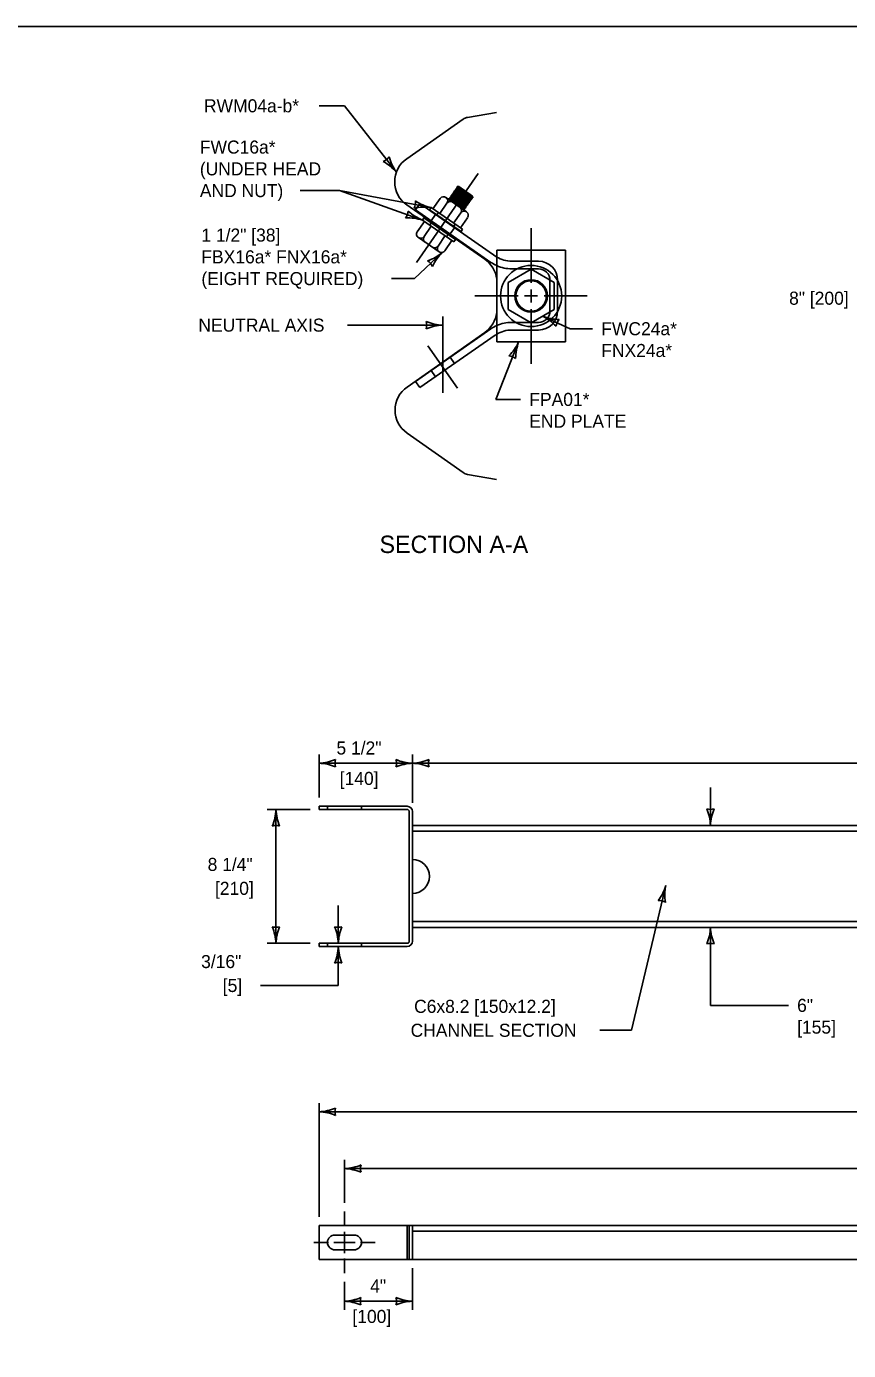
# Model space of a CAD drawing. Extents: x 49991.4 to 50021, y 49987.6 to 50011.4.
# Drawn here: x 50007.52 to 50011.29, y 49992.92 to 49999 of the extents above; entities that cross this region are included whole.
import ezdxf

# ---------------------------------------------------------------- set-up
doc = ezdxf.new("R2010")
doc.units = 0
for name, color, linetype in [('Level 1', 7, 'Continuous'), ('Level 2', 7, 'Continuous'), ('Level 3', 7, 'Continuous'), ('Level 4', 7, 'Continuous'), ('Level 5', 7, 'Continuous')]:
    doc.layers.add(name, color=color, linetype=linetype)

msp = doc.modelspace()

# ---------------------------------------------------------------- linework, layer by layer
at = {"layer": 'Level 1'}
for p, q in [((50009.5226, 49998.573), (50009.2635, 49998.3913)), ((50009.6759, 49998.6042), (50009.5436, 49998.5817)), ((50009.3838, 49998.1614), (50009.4176, 49998.2094)), ((50009.5389, 49998.1471), (50009.4441, 49998.2139)), ((50009.463, 49998.2071), (50009.4563, 49998.2067)), ((50009.4563, 49998.2067), (50009.4667, 49998.198)), ((50009.4684, 49998.2143), (50009.4612, 49998.2134)), ((50009.463, 49998.2071), (50009.4612, 49998.2134)), ((50009.4612, 49998.2134), (50009.526, 49998.163)), ((50009.463, 49998.2071), (50009.5278, 49998.1563)), ((50009.4729, 49998.2215), (50009.4657, 49998.2211)), ((50009.4684, 49998.2143), (50009.4657, 49998.2211)), ((50009.4657, 49998.2211), (50009.531, 49998.1698)), ((50009.4684, 49998.2143), (50009.5332, 49998.163)), ((50009.4779, 49998.2283), (50009.4711, 49998.2278)), ((50009.4729, 49998.2215), (50009.4711, 49998.2278)), ((50009.4711, 49998.2278), (50009.5359, 49998.177)), ((50009.4729, 49998.2215), (50009.5382, 49998.1702)), ((50009.4833, 49998.2355), (50009.4761, 49998.235)), ((50009.4779, 49998.2283), (50009.4761, 49998.235)), ((50009.4761, 49998.235), (50009.5409, 49998.1837)), ((50009.4779, 49998.2283), (50009.5431, 49998.1774)), ((50009.4882, 49998.2427), (50009.4806, 49998.2418)), ((50009.4833, 49998.2355), (50009.4806, 49998.2418)), ((50009.4806, 49998.2418), (50009.5458, 49998.1909)), ((50009.4833, 49998.2355), (50009.5481, 49998.1842)), ((50009.4927, 49998.2494), (50009.486, 49998.249)), ((50009.4882, 49998.2427), (50009.486, 49998.249)), ((50009.486, 49998.249), (50009.5508, 49998.1977)), ((50009.4882, 49998.2427), (50009.553, 49998.1914)), ((50009.4977, 49998.2562), (50009.4909, 49998.2566)), ((50009.4927, 49998.2494), (50009.4909, 49998.2566)), ((50009.4909, 49998.2566), (50009.5562, 49998.2053)), ((50009.4927, 49998.2494), (50009.5575, 49998.1986)), ((50009.4959, 49998.2634), (50009.5611, 49998.2121)), ((50009.5031, 49998.2634), (50009.4959, 49998.2634)), ((50009.4977, 49998.2562), (50009.4959, 49998.2634)), ((50009.4977, 49998.2562), (50009.5629, 49998.2058)), ((50009.5031, 49998.2634), (50009.5679, 49998.2125)), ((50009.5656, 49998.2193), (50009.5031, 49998.2634)), ((50009.5629, 49998.2058), (50009.5562, 49998.2053)), ((50009.5575, 49998.1986), (50009.5562, 49998.2053)), ((50009.5679, 49998.2125), (50009.5611, 49998.2121)), ((50009.5629, 49998.2058), (50009.5611, 49998.2121)), ((50009.5679, 49998.2125), (50009.5656, 49998.2193)), ((50009.2637, 49998.1795), (50009.622, 49997.9301)), ((50009.3237, 49998.1852), (50009.3034, 49998.1564)), ((50009.6509, 49997.9154), (50009.3034, 49998.1564)), ((50009.6774, 49997.9399), (50009.3237, 49998.1852)), ((50009.3685, 49998.1568), (50009.3753, 49998.1672)), ((50009.3685, 49998.1568), (50009.5134, 49998.0574)), ((50009.3753, 49998.1672), (50009.5202, 49998.0677)), ((50009.4157, 49998.1395), (50009.4486, 49998.1873)), ((50009.5278, 49998.1563), (50009.526, 49998.163)), ((50009.5332, 49998.163), (50009.526, 49998.163)), ((50009.5382, 49998.1702), (50009.531, 49998.1698)), ((50009.5332, 49998.163), (50009.531, 49998.1698)), ((50009.5431, 49998.1774), (50009.5359, 49998.177)), ((50009.5382, 49998.1702), (50009.5359, 49998.177)), ((50009.5481, 49998.1842), (50009.5409, 49998.1837)), ((50009.5431, 49998.1774), (50009.5409, 49998.1837)), ((50009.553, 49998.1914), (50009.5458, 49998.1909)), ((50009.5481, 49998.1842), (50009.5458, 49998.1909)), ((50009.5575, 49998.1986), (50009.5508, 49998.1977)), ((50009.553, 49998.1914), (50009.5508, 49998.1977)), ((50009.3449, 49998.1033), (50009.312, 49998.0556)), ((50009.3358, 49998.1096), (50009.3426, 49998.12)), ((50009.3358, 49998.1096), (50009.4807, 49998.0102)), ((50009.3426, 49998.12), (50009.4875, 49998.0205)), ((50009.3697, 49998.0863), (50009.3767, 49998.0966)), ((50009.3758, 49998.1062), (50009.3957, 49998.1352)), ((50009.4024, 49998.1335), (50009.4093, 49998.1438)), ((50009.4791, 49998.0959), (50009.5116, 49998.1423)), ((50009.4792, 49998.0808), (50009.4865, 49998.0908)), ((50009.5107, 49998.0742), (50009.5434, 49998.1207)), ((50009.4126, 49997.9637), (50009.317, 49998.0291)), ((50009.3764, 49998.0817), (50009.3435, 49998.034)), ((50009.4399, 49998.0382), (50009.4074, 49997.9904)), ((50009.4466, 49998.0336), (50009.4538, 49998.0436)), ((50009.4626, 49998.046), (50009.4832, 49998.0746)), ((50009.5134, 49998.0574), (50009.5202, 49998.0677)), ((50009.4717, 49998.0164), (50009.4389, 49997.9688)), ((50009.4807, 49998.0102), (50009.4875, 49998.0205)), ((50009.6774, 49997.9719), (50009.9933, 49997.9719)), ((50009.6774, 49997.5497), (50009.6774, 49997.9719)), ((50009.9933, 49997.9719), (50009.9933, 49997.5497)), ((50009.7301, 49997.8223), (50009.8354, 49997.8837)), ((50009.7301, 49997.6992), (50009.7301, 49997.8223)), ((50009.9407, 49997.8221), (50009.9407, 49997.6992)), ((50009.8354, 49997.6376), (50009.7301, 49997.6992)), ((50009.8354, 49997.6376), (50009.9407, 49997.6992)), ((50009.6506, 49997.6097), (50009.3034, 49997.3683)), ((50009.622, 49997.5933), (50009.265, 49997.3423)), ((50009.6706, 49997.5808), (50009.3237, 49997.34)), ((50009.9933, 49997.5497), (50009.6774, 49997.5497)), ((50009.4627, 49997.479), (50009.4828, 49997.4504)), ((50009.3759, 49997.4187), (50009.3957, 49997.3899)), ((50009.3237, 49997.34), (50009.3034, 49997.3683)), ((50009.2649, 49997.1308), (50009.5226, 49996.9498)), ((50009.5436, 49996.9411), (50009.6759, 49996.9172)), ((50009.2656, 49995.4161), (50008.8604, 49995.4161)), ((50008.8604, 49995.4161), (50008.8604, 49995.4015)), ((50009.2656, 49995.4015), (50008.8604, 49995.4015)), ((50009.2753, 49995.3917), (50009.2753, 49994.7962)), ((50009.29, 49995.3917), (50009.29, 49994.7962)), ((50009.29, 49995.3283), (50014.5227, 49995.3283)), ((50009.29, 49995.3283), (50009.29, 49995.1721)), ((50009.29, 49995.0159), (50009.29, 49994.8597)), ((50009.29, 49994.8597), (50014.5227, 49994.8597)), ((50009.2656, 49994.7864), (50008.8604, 49994.7864)), ((50008.8604, 49994.7718), (50008.8604, 49994.7864)), ((50009.2656, 49994.7718), (50008.8604, 49994.7718)), ((50014.9522, 49993.49), (50008.8604, 49993.49)), ((50008.8604, 49993.49), (50008.8604, 49993.3338)), ((50009.2656, 49993.3338), (50009.2656, 49993.49)), ((50009.29, 49993.49), (50009.29, 49993.3338)), ((50008.9336, 49993.4461), (50009.0215, 49993.4461)), ((50009.0215, 49993.3777), (50008.9336, 49993.3777)), ((50014.9522, 49993.3338), (50008.8604, 49993.3338))]:
    msp.add_line(p, q, dxfattribs=at)
msp.add_lwpolyline([(49999.3835, 49998.9992), (50016.7501, 49998.9992), (50016.7501, 49987.7988), (49999.3835, 49987.7988)], close=True, dxfattribs=at)
msp.add_lwpolyline([(50009.9407, 49997.8221), (50009.8354, 49997.8837)], dxfattribs=at)
for radius in [0.1406, 0.0699]:
    msp.add_circle((50009.8354, 49997.7608), radius, dxfattribs=at)
for centre, radius, start, end in [((50009.5524, 49998.5307), 0.0517, 99.72758, 125.0905), ((50009.3377, 49998.2855), 0.1293, 125.05837, 235.09637), ((50009.4331, 49998.1984), 0.019, 54.63754, 144.63754), ((50009.4334, 49998.1984), 0.0188, 323.73392, 52.86678), ((50009.4643, 49998.176), 0.0193, 55.63697, 144.27069), ((50009.4959, 49998.1537), 0.0194, 323.96325, 53.4977), ((50009.5274, 49998.132), 0.019, 54.83598, 141.39824), ((50009.5278, 49998.1317), 0.019, 324.83598, 54.83598), ((50009.3278, 49998.0448), 0.019, 145.70917, 235.70917), ((50009.3279, 49998.0448), 0.019, 235.34991, 325.34991), ((50009.3594, 49998.0232), 0.0192, 146.74227, 229.68766), ((50009.3917, 49998.0012), 0.0191, 237.70656, 324.13435), ((50009.423, 49997.9795), 0.0189, 145.1428, 235.1428), ((50009.4232, 49997.9794), 0.019, 235.88264, 325.88264), ((50009.5478, 49997.8227), 0.1306, 6.6724, 55.32787), ((50009.7461, 49998.0524), 0.1669, 235.20823, 245.70727), ((50009.5479, 49997.7006), 0.1304, 304.64367, 353.29913), ((50009.746, 49997.4727), 0.1669, 114.24379, 124.83291), ((50009.746, 49997.4727), 0.1318, 121.33081, 124.90042), ((50009.3394, 49997.2365), 0.1293, 125.10071, 234.84685), ((50009.5525, 49996.9921), 0.0518, 234.80447, 260.16739), ((50009.2656, 49995.3917), 0.0244, 0, 90), ((50009.2656, 49995.3917), 0.00976, 0, 90), ((50009.29, 49995.094), 0.0781, 270, 90), ((50009.2656, 49994.7962), 0.0244, 270, 0), ((50009.2656, 49994.7962), 0.00976, 270, 0), ((50008.9336, 49993.4119), 0.0342, 90, 270), ((50009.0215, 49993.4119), 0.0342, 270, 90)]:
    msp.add_arc(centre, radius, start, end, dxfattribs=at)
at = {"layer": 'Level 3'}
for p, q in [((50008.8618, 49998.6347), (50008.9772, 49998.6347)), ((50008.9772, 49998.6347), (50009.2162, 49998.3295)), ((50008.7736, 49998.2451), (50008.9553, 49998.2451)), ((50008.9553, 49998.2451), (50009.3358, 49998.1096)), ((50009.3753, 49998.1672), (50008.9553, 49998.2451)), ((50009.2992, 49997.8407), (50009.427, 49997.9608)), ((50009.1931, 49997.8407), (50009.2992, 49997.8407)), ((50009.429, 49997.3157), (50009.429, 49997.6669)), ((50010.0152, 49997.6105), (50009.8876, 49997.6681)), ((50008.9916, 49997.6269), (50009.429, 49997.6269)), ((50010.118, 49997.6105), (50010.0152, 49997.6105)), ((50009.6732, 49997.2855), (50009.7781, 49997.5497)), ((50009.7871, 49997.2855), (50009.6732, 49997.2855)), ((50008.8604, 49995.4561), (50008.8605, 49995.654)), ((50009.29, 49995.4317), (50009.2901, 49995.654)), ((50008.8605, 49995.614), (50009.2901, 49995.614)), ((50009.2901, 49995.614), (50014.5228, 49995.614)), ((50010.6598, 49995.5017), (50010.6598, 49995.3283)), ((50008.8204, 49995.4015), (50008.6225, 49995.4016)), ((50008.6625, 49994.7865), (50008.6625, 49995.4015)), ((50010.2969, 49994.3868), (50010.454, 49995.0527)), ((50008.9491, 49994.9598), (50008.9491, 49994.7864)), ((50010.6598, 49994.5013), (50010.6598, 49994.8597)), ((50008.8204, 49994.7864), (50008.6225, 49994.7865)), ((50008.9491, 49994.7718), (50008.9491, 49994.5926)), ((50008.5907, 49994.5926), (50008.9491, 49994.5926)), ((50010.6598, 49994.5013), (50011.0182, 49994.5013)), ((50010.2969, 49994.3868), (50010.152, 49994.3868)), ((50008.8604, 49993.53), (50008.8604, 49994.0526)), ((50008.8604, 49994.0126), (50014.9522, 49994.0126)), ((50008.9775, 49993.5934), (50008.9776, 49993.7913)), ((50008.9776, 49993.7513), (50014.8351, 49993.7513)), ((50009.29, 49993.2938), (50009.29, 49993.1019)), ((50008.9773, 49993.1019), (50008.9775, 49993.2304)), ((50008.9773, 49993.1419), (50009.29, 49993.1419))]:
    msp.add_line(p, q, dxfattribs=at)
for centre, radius, start, end in [((50009.1371, 49998.4305), 0.0548, 290.19918, 325.92154), ((50009.3967, 49998.4593), 0.2223, 195.51638, 215.69988), ((50009.04, 49998.177), 0.233, 40.88768, 60.13753), ((50009.2151, 49998.1526), 0.0548, 322.5274, 358.24976), ((50009.419, 49998.3157), 0.2223, 227.8446, 248.0281), ((50009.2492, 49998.1906), 0.0548, 331.62434, 7.3467), ((50009.3441, 49997.9363), 0.233, 82.31283, 101.56268), ((50009.4248, 49998.3839), 0.2223, 236.94153, 257.12504), ((50009.2686, 49997.8865), 0.233, 73.2159, 92.46575), ((50009.2837, 49998.1308), 0.2223, 289.94938, 310.13289), ((50009.3325, 49997.8742), 0.0548, 24.63219, 60.35455), ((50009.5927, 49997.797), 0.233, 135.32068, 154.57053), ((50009.7879, 49997.4694), 0.2223, 43.16109, 63.34459), ((50009.9729, 49997.8849), 0.233, 248.53239, 267.78224), ((50009.4382, 49997.849), 0.2223, 247.45601, 267.63952), ((50009.3008, 49997.6269), 0.0548, 342.13882, 17.86118), ((50009.4405, 49997.3941), 0.233, 92.82731, 112.07716), ((50010.0045, 49997.6153), 0.0548, 137.84389, 173.56626), ((50009.5769, 49997.6442), 0.2223, 314.6559, 334.83941), ((50009.9971, 49997.4701), 0.233, 160.0272, 179.27705), ((50009.7284, 49997.4315), 0.0548, 49.33871, 85.06107), ((50008.849, 49995.8467), 0.233, 272.82731, 292.07716), ((50008.8514, 49995.3919), 0.2223, 67.45601, 87.63952), ((50008.9887, 49995.614), 0.0548, 162.13882, 197.86118), ((50009.2992, 49995.8361), 0.2223, 247.45601, 267.63952), ((50009.1618, 49995.614), 0.0548, 342.13882, 17.86118), ((50009.3016, 49995.3813), 0.233, 92.82731, 112.07716), ((50009.2786, 49995.8467), 0.233, 272.82731, 292.07716), ((50009.2809, 49995.3919), 0.2223, 67.45601, 87.63952), ((50009.4183, 49995.614), 0.0548, 162.13882, 197.86118), ((50008.4404, 49995.4107), 0.2223, 337.45601, 357.63952), ((50008.8953, 49995.413), 0.233, 182.82731, 202.07716), ((50010.4377, 49995.3191), 0.2223, 2.36048, 22.54399), ((50010.6598, 49995.4565), 0.0548, 252.13882, 287.86118), ((50010.8925, 49995.3168), 0.233, 157.92284, 177.17269), ((50008.6625, 49995.2733), 0.0548, 72.13882, 107.86118), ((50010.2399, 49995.1126), 0.2223, 324.18685, 344.37036), ((50010.6831, 49995.0104), 0.233, 169.55815, 188.808), ((50010.4245, 49994.9279), 0.0548, 58.86966, 94.59202), ((50008.6625, 49994.9147), 0.0548, 252.13882, 287.86118), ((50008.4298, 49994.775), 0.233, 2.82731, 22.07716), ((50008.8847, 49994.7774), 0.2223, 157.45601, 177.63952), ((50008.9491, 49994.9147), 0.0548, 252.13882, 287.86118), ((50008.7164, 49994.7749), 0.233, 2.82731, 22.07716), ((50009.1712, 49994.7773), 0.2223, 157.45601, 177.63952), ((50010.4377, 49994.8688), 0.2223, 337.45601, 357.63952), ((50010.8925, 49994.8712), 0.233, 182.82731, 202.07716), ((50008.727, 49994.781), 0.2223, 337.45601, 357.63952), ((50009.1818, 49994.7833), 0.233, 182.82731, 202.07716), ((50010.6598, 49994.7314), 0.0548, 72.13882, 107.86118), ((50008.9491, 49994.6436), 0.0548, 72.13882, 107.86118), ((50008.8489, 49994.2453), 0.233, 272.82731, 292.07716), ((50008.8513, 49993.7905), 0.2223, 67.45601, 87.63952), ((50008.9886, 49994.0126), 0.0548, 162.13882, 197.86118), ((50008.9661, 49993.984), 0.233, 272.82731, 292.07716), ((50009.1058, 49993.7513), 0.0548, 162.13882, 197.86118), ((50008.9684, 49993.5292), 0.2223, 67.45601, 87.63952), ((50008.9681, 49993.364), 0.2223, 272.36048, 292.54399), ((50009.1055, 49993.1419), 0.0548, 162.13882, 197.86118), ((50009.1618, 49993.1419), 0.0548, 342.13882, 17.86118), ((50009.3015, 49993.3746), 0.233, 247.92284, 267.17269), ((50008.9658, 49992.9092), 0.233, 67.92284, 87.17269), ((50009.2991, 49992.9198), 0.2223, 92.36048, 112.54399)]:
    msp.add_arc(centre, radius, start, end, dxfattribs=at)
at = {"layer": 'Level 4'}
for p, q in [((50009.746, 49997.9207), (50009.8693, 49997.9207)), ((50009.746, 49997.8856), (50009.8693, 49997.8856)), ((50009.9221, 49997.6924), (50009.9221, 49997.833)), ((50009.9572, 49997.6924), (50009.9572, 49997.8328)), ((50009.746, 49997.6396), (50009.8693, 49997.6396)), ((50009.746, 49997.6045), (50009.8693, 49997.6045)), ((50008.8995, 49995.4015), (50008.8995, 49995.4161)), ((50009.0557, 49995.4015), (50009.0557, 49995.4161)), ((50009.29, 49995.3015), (50014.5227, 49995.3015)), ((50009.29, 49994.8864), (50014.5227, 49994.8864)), ((50008.8995, 49994.7718), (50008.8995, 49994.7864)), ((50009.0557, 49994.7718), (50009.0557, 49994.7864)), ((50009.2753, 49993.49), (50009.2753, 49993.3338)), ((50009.29, 49993.4632), (50014.5227, 49993.4632))]:
    msp.add_line(p, q, dxfattribs=at)
msp.add_circle((50009.8354, 49997.7608), 0.0748, dxfattribs=at)
for centre, radius, start, end in [((50009.746, 49998.0525), 0.1318, 238.66919, 270), ((50009.8693, 49997.8328), 0.0879, 0, 90), ((50009.746, 49998.0525), 0.1669, 245.75621, 270), ((50009.8693, 49997.8328), 0.0528, 0, 90), ((50009.8693, 49997.6924), 0.0528, 270, 0), ((50009.8693, 49997.6924), 0.0879, 270, 0), ((50009.746, 49997.4727), 0.1669, 90, 114.24379), ((50009.746, 49997.4727), 0.1318, 90, 121.33081)]:
    msp.add_arc(centre, radius, start, end, dxfattribs=at)
at = {"layer": 'Level 5'}
for p, q in [((50009.3084, 49997.914), (50009.5914, 49998.3234)), ((50009.8354, 49998.0719), (50009.8354, 49997.8208)), ((50009.8354, 49997.7908), (50009.8354, 49997.7308)), ((50009.5774, 49997.7608), (50009.7753, 49997.7608)), ((50009.8053, 49997.7608), (50009.8653, 49997.7608)), ((50009.8953, 49997.7608), (50010.0933, 49997.7608)), ((50009.8354, 49997.7008), (50009.8354, 49997.4497)), ((50009.3613, 49997.5322), (50009.4963, 49997.338)), ((50008.9775, 49993.486), (50008.9775, 49993.5534)), ((50008.9775, 49993.3628), (50008.9775, 49993.461)), ((50008.836, 49993.4119), (50008.9034, 49993.4119)), ((50008.9284, 49993.4119), (50009.0266, 49993.4119)), ((50009.0516, 49993.4119), (50009.119, 49993.4119)), ((50008.9775, 49993.3378), (50008.9775, 49993.2704))]:
    msp.add_line(p, q, dxfattribs=at)

# ---------------------------------------------------------------- texts
at = {"layer": 'Level 2'}
for s, height, p in [('RWM04a-b*', 0.06, (50008.3317, 49998.6047)), ('FWC16a*', 0.06, (50008.3127, 49998.4151)), ('(UNDER HEAD', 0.06, (50008.3127, 49998.3151)), ('AND NUT)', 0.06, (50008.3127, 49998.2151)), ('1 1/2" [38] ', 0.06, (50008.3197, 49998.0107)), ('FBX16a* FNX16a*', 0.06, (50008.3197, 49997.9107)), ('(EIGHT REQUIRED)', 0.06, (50008.3197, 49997.8107)), ('8" [200]', 0.06, (50011.0214, 49997.7207)), ('NEUTRAL AXIS', 0.06, (50008.3058, 49997.5969)), ('FWC24a*', 0.06, (50010.158, 49997.5805)), ('FNX24a*', 0.06, (50010.158, 49997.4805)), ('FPA01*', 0.06, (50009.8271, 49997.2555)), ('END PLATE', 0.06, (50009.8271, 49997.1555)), ('SECTION A-A', 0.08, (50009.1387, 49996.5797)), ('5 1/2"', 0.06, (50008.9406, 49995.654)), ('[140]', 0.06, (50008.9556, 49995.514)), ('8 1/4"', 0.06, (50008.3484, 49995.119)), ('[210]', 0.06, (50008.3821, 49995.009)), ('3/16"', 0.06, (50008.3186, 49994.6726)), ('[5]', 0.06, (50008.418, 49994.5626)), ('C6x8.2 [150x12.2] ', 0.06, (50009.2975, 49994.4668)), ('6"', 0.06, (50011.0582, 49994.4713)), ('[155]', 0.06, (50011.0582, 49994.3713)), ('CHANNEL SECTION', 0.06, (50009.2815, 49994.3568)), ('4"', 0.06, (50009.0956, 49993.1819)), ('[100]', 0.06, (50009.0139, 49993.0419))]:
    msp.add_text(s, height=height, dxfattribs=at).set_placement(p)

doc.saveas('drawing.dxf')
